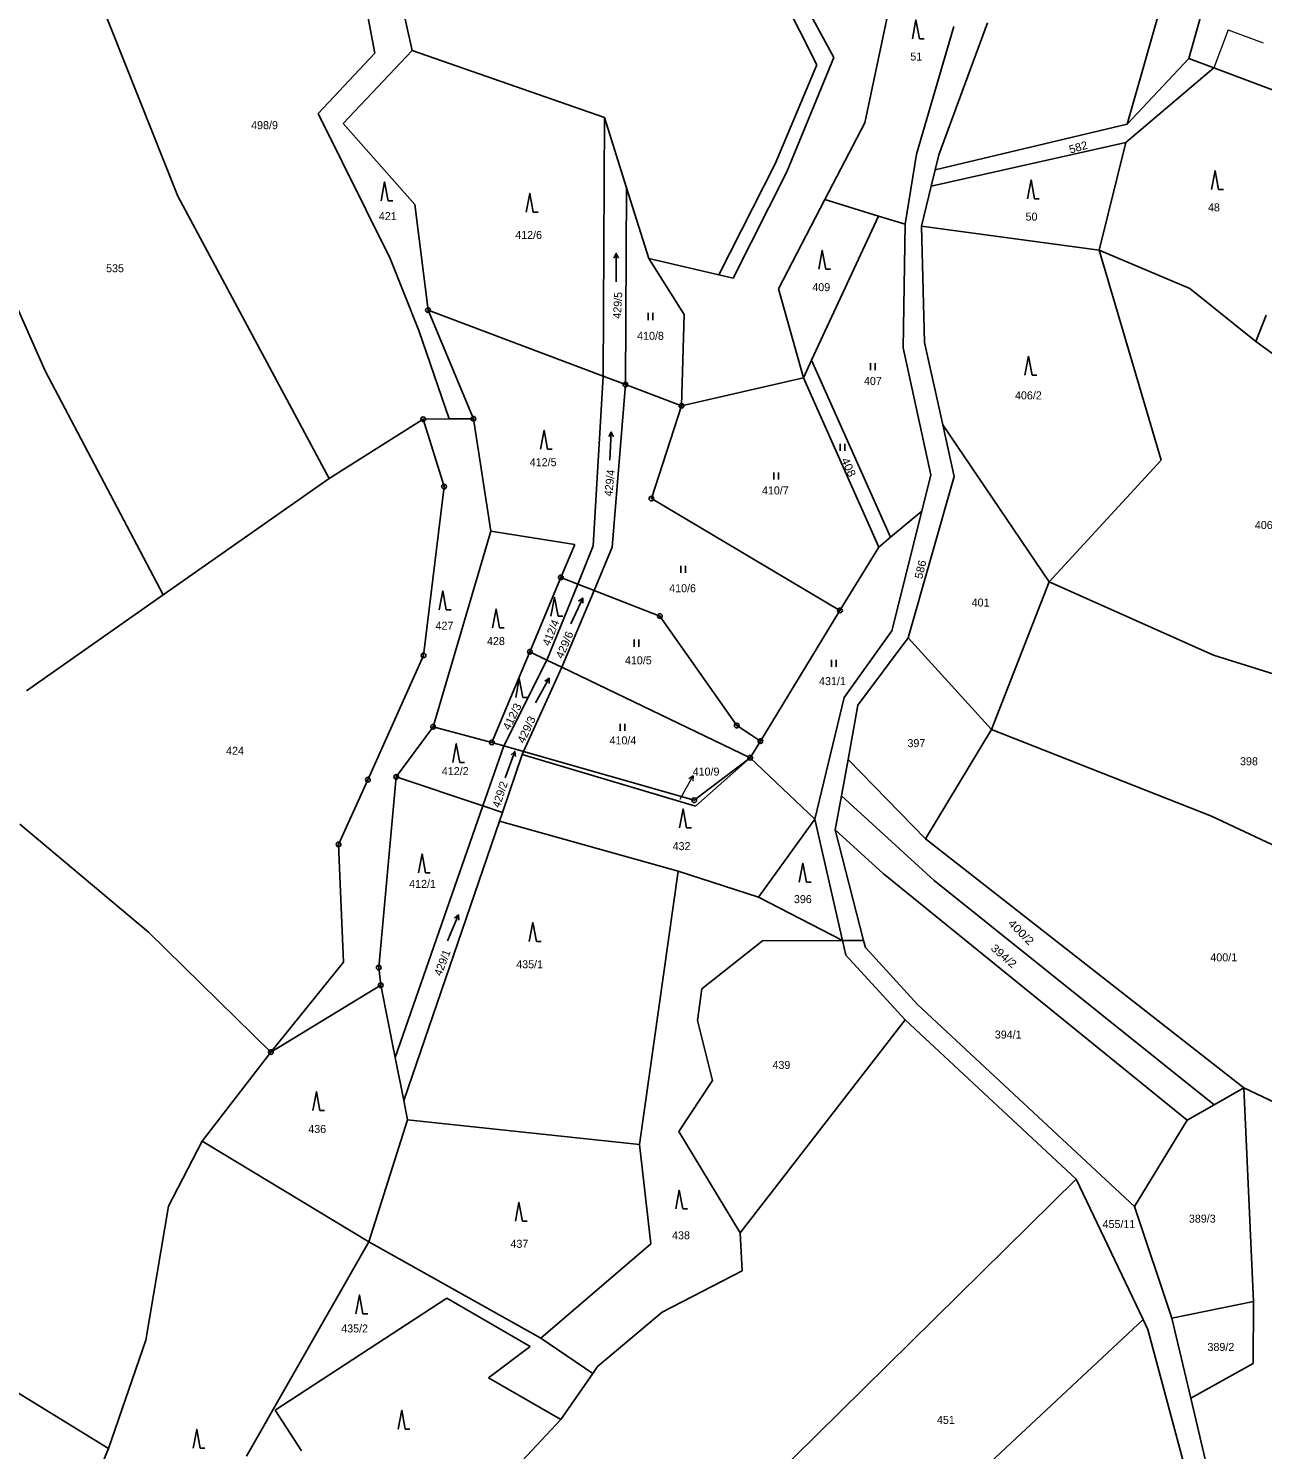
# Model space of a CAD drawing. Extents: x -664548 to -662415, y -1069720 to -1068208.
# Drawn here: x -663871.7 to -663609.5, y -1069397.8 to -1069095.9 of the extents above; entities that cross this region are included whole.
import ezdxf

# ---------------------------------------------------------------- set-up
doc = ezdxf.new("R2010")
doc.units = 0
doc.header["$LTSCALE"] = 0.68
for name, color, linetype, lineweight in [('1', 7, 'Continuous', 25), ('3', 7, 'Continuous', 25), ('4', 7, 'Continuous', 13), ('7', 7, 'Continuous', 13), ('8', 7, 'Continuous', 25)]:
    doc.layers.add(name, color=color, linetype=linetype, lineweight=lineweight)
doc.layers.add('2', color=7, linetype='Continuous')

msp = doc.modelspace()

# ---------------------------------------------------------------- linework, layer by layer
at = {"layer": '1'}
for p, q in [((-663638.3, -1069116.25), (-663622.82, -1069062.07)), ((-663865.77, -1069066.56), (-663839.98, -1069131.55)), ((-663616.65, -1069071.57), (-663625.2, -1069102.36)), ((-663801.58, -1069082.65), (-663798.08, -1069101.18)), ((-663790.14, -1069100.67), (-663794.6, -1069080.65)), ((-663715.38, -1069081.53), (-663704.24, -1069103.68)), ((-663711.53, -1069081.92), (-663700.58, -1069102.12)), ((-663694.06, -1069115.97), (-663686.64, -1069081.11)), ((-663678.33, -1069122.82), (-663667.95, -1069094.79)), ((-663899.9, -1069096.97), (-663868.16, -1069168.67)), ((-663675.12, -1069095.52), (-663683.05, -1069122.67)), ((-663804.84, -1069116.14), (-663790.14, -1069100.67)), ((-663749.29, -1069114.9), (-663790.14, -1069100.67)), ((-663798.08, -1069101.18), (-663810.11, -1069114.01)), ((-663704.24, -1069103.68), (-663713.1, -1069124.73)), ((-663700.58, -1069102.12), (-663710.58, -1069126.44)), ((-663625.2, -1069102.36), (-663638.3, -1069116.25)), ((-663625.2, -1069102.36), (-663619.9, -1069104.35)), ((-663638.58, -1069120.21), (-663619.9, -1069104.35)), ((-663619.9, -1069104.35), (-663602.12, -1069111.05)), ((-663810.11, -1069114.01), (-663794.88, -1069144.81)), ((-663789.58, -1069133.35), (-663804.84, -1069116.14)), ((-663749.63, -1069169.82), (-663749.29, -1069114.9)), ((-663749.29, -1069114.9), (-663744.62, -1069129.84)), ((-663702.52, -1069132.27), (-663694.06, -1069115.97)), ((-663638.3, -1069116.25), (-663679.1, -1069126)), ((-663638.58, -1069120.21), (-663679.93, -1069129.45)), ((-663644.23, -1069143.02), (-663638.58, -1069120.21)), ((-663713.1, -1069124.73), (-663725.04, -1069148.29)), ((-663683.05, -1069122.67), (-663685.44, -1069137.54)), ((-663679.1, -1069126), (-663678.33, -1069122.82)), ((-663710.58, -1069126.44), (-663722.02, -1069148.99)), ((-663679.93, -1069129.45), (-663679.1, -1069126)), ((-663744.88, -1069171.62), (-663744.62, -1069129.84)), ((-663744.62, -1069129.84), (-663739.93, -1069144.81)), ((-663681.98, -1069137.94), (-663679.93, -1069129.45)), ((-663807.82, -1069191.54), (-663839.98, -1069131.55)), ((-663786.81, -1069155.78), (-663789.58, -1069133.35)), ((-663712.38, -1069151.25), (-663702.52, -1069132.27)), ((-663691.09, -1069135.8), (-663702.52, -1069132.27)), ((-663705.32, -1069166.39), (-663691.09, -1069135.8)), ((-663685.44, -1069137.54), (-663691.09, -1069135.8)), ((-663685.44, -1069137.54), (-663685.91, -1069163.82)), ((-663681.35, -1069162.63), (-663681.98, -1069137.94)), ((-663644.23, -1069143.02), (-663681.98, -1069137.94)), ((-663644.23, -1069143.02), (-663624.96, -1069151.22)), ((-663631.05, -1069187.68), (-663644.23, -1069143.02)), ((-663794.88, -1069144.81), (-663788.78, -1069160.08)), ((-663725.04, -1069148.29), (-663739.93, -1069144.81)), ((-663739.93, -1069144.81), (-663732.4, -1069156.73)), ((-663722.02, -1069148.99), (-663725.04, -1069148.29)), ((-663707.06, -1069170.14), (-663712.38, -1069151.25)), ((-663624.96, -1069151.22), (-663610.98, -1069162.48)), ((-663777.17, -1069178.85), (-663786.81, -1069155.78)), ((-663786.81, -1069155.78), (-663749.63, -1069169.82)), ((-663732.4, -1069156.73), (-663732.98, -1069176.11)), ((-663610.98, -1069162.48), (-663608.81, -1069156.86)), ((-663788.78, -1069160.08), (-663782.3, -1069178.9)), ((-663685.91, -1069163.82), (-663679.99, -1069190.79)), ((-663677.47, -1069180.17), (-663681.35, -1069162.63)), ((-663610.98, -1069162.48), (-663593.01, -1069175.48)), ((-663707.06, -1069170.14), (-663705.32, -1069166.39)), ((-663688.6, -1069204.04), (-663705.32, -1069166.39)), ((-663843.03, -1069216.25), (-663868.16, -1069168.67)), ((-663751.72, -1069205.89), (-663749.63, -1069169.82)), ((-663749.63, -1069169.82), (-663744.88, -1069171.62)), ((-663732.98, -1069176.11), (-663707.06, -1069170.14)), ((-663691.08, -1069206.11), (-663707.06, -1069170.14)), ((-663747.7, -1069206.16), (-663744.88, -1069171.62)), ((-663744.88, -1069171.62), (-663732.98, -1069176.11)), ((-663732.98, -1069176.11), (-663739.35, -1069195.83)), ((-663787.83, -1069178.96), (-663807.82, -1069191.54)), ((-663787.83, -1069178.96), (-663782.3, -1069178.9)), ((-663783.39, -1069193.26), (-663787.83, -1069178.96)), ((-663782.3, -1069178.9), (-663777.17, -1069178.85)), ((-663777.17, -1069178.85), (-663773.46, -1069202.72)), ((-663654.86, -1069213.5), (-663677.47, -1069180.17)), ((-663675.05, -1069191.11), (-663677.47, -1069180.17)), ((-663654.86, -1069213.5), (-663631.05, -1069187.68)), ((-663807.82, -1069191.54), (-663843.03, -1069216.25)), ((-663684.82, -1069225.41), (-663675.05, -1069191.11)), ((-663679.99, -1069190.79), (-663681.92, -1069198.47)), ((-663787.74, -1069229.14), (-663783.39, -1069193.26)), ((-663739.35, -1069195.83), (-663699.3, -1069219.59)), ((-663688.6, -1069204.04), (-663681.92, -1069198.47)), ((-663681.92, -1069198.47), (-663688.31, -1069223.94)), ((-663773.46, -1069202.72), (-663785.73, -1069244.3)), ((-663773.46, -1069202.72), (-663755.65, -1069205.58)), ((-663755.65, -1069205.58), (-663758.58, -1069212.58)), ((-663751.72, -1069205.89), (-663755, -1069213.98)), ((-663747.7, -1069206.16), (-663751.55, -1069215.32)), ((-663699.3, -1069219.59), (-663691.08, -1069206.11)), ((-663691.08, -1069206.11), (-663688.6, -1069204.04)), ((-663758.58, -1069212.58), (-663765.18, -1069228.35)), ((-663755, -1069213.98), (-663758.58, -1069212.58)), ((-663755, -1069213.98), (-663761.54, -1069230.11)), ((-663751.55, -1069215.32), (-663758.39, -1069231.63)), ((-663751.55, -1069215.32), (-663755, -1069213.98)), ((-663737.55, -1069220.78), (-663751.55, -1069215.32)), ((-663667.09, -1069244.89), (-663654.86, -1069213.5)), ((-663620, -1069229.07), (-663654.86, -1069213.5)), ((-663843.03, -1069216.25), (-663872.12, -1069236.66)), ((-663737.55, -1069220.78), (-663721.23, -1069244.05)), ((-663716.2, -1069247.32), (-663699.3, -1069219.59)), ((-663688.31, -1069223.94), (-663698.38, -1069238.05)), ((-663695.51, -1069239.72), (-663684.82, -1069225.41)), ((-663684.82, -1069225.41), (-663667.09, -1069244.89)), ((-663799.57, -1069255.53), (-663787.74, -1069229.14)), ((-663765.18, -1069228.35), (-663773.24, -1069247.62)), ((-663761.54, -1069230.11), (-663770.69, -1069248.35)), ((-663761.54, -1069230.11), (-663765.18, -1069228.35)), ((-663758.39, -1069231.63), (-663761.54, -1069230.11)), ((-663607.07, -1069233.13), (-663620, -1069229.07)), ((-663758.39, -1069231.63), (-663766.5, -1069249.55)), ((-663718.38, -1069250.89), (-663758.39, -1069231.63)), ((-663698.38, -1069238.05), (-663704.68, -1069263.89)), ((-663697.6, -1069251.24), (-663695.51, -1069239.72)), ((-663785.73, -1069244.3), (-663793.55, -1069254.93)), ((-663773.24, -1069247.62), (-663785.73, -1069244.3)), ((-663721.23, -1069244.05), (-663718.07, -1069246.07)), ((-663718.07, -1069246.07), (-663716.2, -1069247.32)), ((-663667.09, -1069244.89), (-663681.14, -1069268.13)), ((-663667.09, -1069244.89), (-663620.38, -1069263.31)), ((-663775.13, -1069261.09), (-663770.69, -1069248.35)), ((-663770.69, -1069248.35), (-663773.24, -1069247.62)), ((-663766.5, -1069249.55), (-663770.69, -1069248.35)), ((-663718.38, -1069250.89), (-663716.2, -1069247.32)), ((-663766.79, -1069250.19), (-663771, -1069262.47)), ((-663766.5, -1069249.55), (-663766.79, -1069250.19)), ((-663729.97, -1069261.19), (-663766.79, -1069250.19)), ((-663730.27, -1069259.91), (-663766.5, -1069249.55)), ((-663730.27, -1069259.91), (-663718.38, -1069250.89)), ((-663718.38, -1069250.89), (-663729.97, -1069261.19)), ((-663704.68, -1069263.89), (-663718.38, -1069250.89)), ((-663699.01, -1069258.98), (-663697.6, -1069251.24)), ((-663681.14, -1069268.13), (-663697.6, -1069251.24)), ((-663793.55, -1069254.93), (-663797.26, -1069295.46)), ((-663775.13, -1069261.09), (-663793.55, -1069254.93)), ((-663805.8, -1069269.28), (-663799.57, -1069255.53)), ((-663793.8, -1069314.55), (-663775.13, -1069261.09)), ((-663771, -1069262.47), (-663775.13, -1069261.09)), ((-663700.32, -1069266.21), (-663699.01, -1069258.98)), ((-663679.3, -1069276.93), (-663699.01, -1069258.98)), ((-663771, -1069262.47), (-663771.65, -1069264.35)), ((-663716.58, -1069280.51), (-663704.68, -1069263.89)), ((-663704.68, -1069263.89), (-663698.75, -1069289.7)), ((-663620.38, -1069263.31), (-663570.12, -1069287)), ((-663846.2, -1069287.9), (-663873.52, -1069264.98)), ((-663771.65, -1069264.35), (-663791.98, -1069323.66)), ((-663733.7, -1069274.94), (-663771.65, -1069264.35)), ((-663690.11, -1069275.48), (-663700.32, -1069266.21)), ((-663694.28, -1069289.68), (-663700.32, -1069266.21)), ((-663804.74, -1069294.32), (-663805.8, -1069269.28)), ((-663613.49, -1069320.97), (-663681.14, -1069268.13)), ((-663741.89, -1069333.02), (-663733.7, -1069274.94)), ((-663733.7, -1069274.94), (-663716.58, -1069280.51)), ((-663625.56, -1069327.85), (-663690.11, -1069275.48)), ((-663619.83, -1069324.58), (-663679.3, -1069276.93)), ((-663820.17, -1069313.41), (-663846.2, -1069287.9)), ((-663715.75, -1069289.76), (-663728.63, -1069299.99)), ((-663694.28, -1069289.68), (-663698.75, -1069289.7)), ((-663698.75, -1069289.7), (-663698.04, -1069292.8)), ((-663693.89, -1069291.21), (-663694.28, -1069289.68)), ((-663682.82, -1069303.32), (-663693.89, -1069291.21)), ((-663820.17, -1069313.41), (-663804.74, -1069294.32)), ((-663685.43, -1069306.57), (-663698.04, -1069292.8)), ((-663797.26, -1069295.46), (-663796.86, -1069299.2)), ((-663796.86, -1069299.2), (-663820.17, -1069313.41)), ((-663796.86, -1069299.2), (-663793.8, -1069314.55)), ((-663728.63, -1069299.99), (-663729.57, -1069306.68)), ((-663636.71, -1069346.23), (-663682.82, -1069303.32)), ((-663729.57, -1069306.68), (-663726.4, -1069319.42)), ((-663720.5, -1069351.82), (-663685.43, -1069306.57)), ((-663649.12, -1069340.38), (-663685.43, -1069306.57)), ((-663820.17, -1069313.41), (-663834.81, -1069332.34)), ((-663793.8, -1069314.55), (-663791.98, -1069323.66)), ((-663726.4, -1069319.42), (-663733.53, -1069330.29)), ((-663613.49, -1069320.97), (-663619.83, -1069324.58)), ((-663613.49, -1069320.97), (-663604.26, -1069325.38)), ((-663611.5, -1069366.37), (-663613.49, -1069320.97)), ((-663791.98, -1069323.66), (-663791.16, -1069327.76)), ((-663619.83, -1069324.58), (-663625.56, -1069327.85)), ((-663791.16, -1069327.76), (-663799.35, -1069353.72)), ((-663791.16, -1069327.76), (-663741.89, -1069333.02)), ((-663733.53, -1069330.29), (-663720.5, -1069351.82)), ((-663625.56, -1069327.85), (-663636.71, -1069346.23)), ((-663834.81, -1069332.34), (-663841.91, -1069346.1)), ((-663799.35, -1069353.72), (-663834.81, -1069332.34)), ((-663741.89, -1069333.02), (-663739.46, -1069354.12)), ((-663730.63, -1069420.68), (-663649.12, -1069340.38)), ((-663649.12, -1069340.38), (-663634.92, -1069370.21)), ((-663841.91, -1069346.1), (-663846.72, -1069374.59)), ((-663628.78, -1069369.92), (-663636.71, -1069346.23)), ((-663799.35, -1069353.72), (-663825.36, -1069399.27)), ((-663799.35, -1069353.72), (-663762.86, -1069374.17)), ((-663739.46, -1069354.12), (-663762.86, -1069374.17)), ((-663720.5, -1069351.82), (-663720.07, -1069359.88)), ((-663720.07, -1069359.88), (-663737.05, -1069368.67)), ((-663782.8, -1069365.67), (-663819.27, -1069389.47)), ((-663782.8, -1069365.67), (-663765.09, -1069375.97)), ((-663611.5, -1069366.37), (-663628.78, -1069369.92)), ((-663611.54, -1069379.52), (-663611.5, -1069366.37)), ((-663737.05, -1069368.67), (-663750.8, -1069380.19)), ((-663718.73, -1069448.55), (-663634.92, -1069370.21)), ((-663634.92, -1069370.21), (-663633.89, -1069372.36)), ((-663633.89, -1069372.36), (-663626.15, -1069401.37)), ((-663624.79, -1069386.91), (-663628.78, -1069369.92)), ((-663846.72, -1069374.59), (-663854.69, -1069397.6)), ((-663762.86, -1069374.17), (-663751.82, -1069381.66)), ((-663886.73, -1069377.97), (-663854.69, -1069397.6)), ((-663765.09, -1069375.97), (-663773.97, -1069382.57)), ((-663751.82, -1069381.66), (-663758.57, -1069391.42)), ((-663750.8, -1069380.19), (-663751.82, -1069381.66)), ((-663611.54, -1069379.52), (-663624.79, -1069386.91)), ((-663758.57, -1069391.42), (-663773.97, -1069382.57)), ((-663620.97, -1069403.18), (-663624.79, -1069386.91)), ((-663819.27, -1069389.47), (-663813.67, -1069398.07)), ((-663791.3, -1069426.25), (-663758.57, -1069391.42)), ((-663854.69, -1069397.6), (-663858.93, -1069407.87))]:
    msp.add_line(p, q, dxfattribs=at)
msp.add_lwpolyline([(-663716.58, -1069280.51), (-663698.75, -1069289.7), (-663715.75, -1069289.76)], dxfattribs=at)
at = {"layer": '3'}
for p, q in [((-663682.43, -1069098.15), (-663681.434, -1069098.15)), ((-663618.87, -1069130.17), (-663617.874, -1069130.17)), ((-663795.28, -1069132.56), (-663794.284, -1069132.56)), ((-663657.96, -1069132.12), (-663656.964, -1069132.12)), ((-663764.44, -1069134.99), (-663763.444, -1069134.99)), ((-663746.841, -1069143.743), (-663746.34, -1069144.72)), ((-663702.31, -1069147.09), (-663701.314, -1069147.09)), ((-663740.081, -1069157.89), (-663740.081, -1069156.39)), ((-663739.08, -1069157.89), (-663739.08, -1069156.39)), ((-663692.801, -1069168.52), (-663692.801, -1069167.02)), ((-663691.8, -1069168.52), (-663691.8, -1069167.02)), ((-663658.51, -1069169.59), (-663657.514, -1069169.59)), ((-663747.884, -1069181.677), (-663747.434, -1069182.679)), ((-663761.42, -1069185.29), (-663760.424, -1069185.29)), ((-663699.271, -1069185.69), (-663699.271, -1069184.19)), ((-663698.27, -1069185.69), (-663698.27, -1069184.19)), ((-663713.331, -1069191.76), (-663713.331, -1069190.26)), ((-663712.33, -1069191.76), (-663712.33, -1069190.26)), ((-663733.091, -1069211.57), (-663733.091, -1069210.07)), ((-663732.09, -1069211.57), (-663732.09, -1069210.07)), ((-663753.957, -1069216.969), (-663753.916, -1069218.067)), ((-663782.92, -1069219.45), (-663781.924, -1069219.45)), ((-663759.19, -1069220.8), (-663758.194, -1069220.8)), ((-663771.61, -1069223.29), (-663770.614, -1069223.29)), ((-663743.041, -1069227.28), (-663743.041, -1069225.78)), ((-663742.04, -1069227.28), (-663742.04, -1069225.78)), ((-663701.131, -1069231.54), (-663701.131, -1069230.04)), ((-663700.13, -1069231.54), (-663700.13, -1069230.04)), ((-663761.05, -1069233.975), (-663761.085, -1069235.073)), ((-663766.67, -1069238.06), (-663765.674, -1069238.06)), ((-663745.971, -1069245.14), (-663745.971, -1069243.64)), ((-663744.97, -1069245.14), (-663744.97, -1069243.64)), ((-663780.05, -1069251.91), (-663779.054, -1069251.91)), ((-663768.37, -1069249.518), (-663768.233, -1069250.607)), ((-663731.87, -1069265.73), (-663730.874, -1069265.73)), ((-663787.32, -1069275.31), (-663786.324, -1069275.31)), ((-663706.45, -1069277.29), (-663705.454, -1069277.29)), ((-663780.333, -1069284.276), (-663780.253, -1069285.371)), ((-663763.8, -1069289.88), (-663762.804, -1069289.88)), ((-663809.78, -1069325.83), (-663808.784, -1069325.83)), ((-663732.68, -1069346.73), (-663731.684, -1069346.73)), ((-663766.76, -1069349.33), (-663765.764, -1069349.33)), ((-663800.62, -1069369), (-663799.624, -1069369)), ((-663791.64, -1069393.49), (-663790.644, -1069393.49)), ((-663835.18, -1069397.54), (-663834.184, -1069397.54))]:
    msp.add_line(p, q, dxfattribs=at)
for points in [[(-663682.43, -1069098.15), (-663683.18, -1069094.15), (-663683.93, -1069098.15)], [(-663657.96, -1069132.12), (-663658.71, -1069128.12), (-663659.46, -1069132.12)], [(-663618.87, -1069130.17), (-663619.62, -1069126.17), (-663620.37, -1069130.17)], [(-663795.28, -1069132.56), (-663796.03, -1069128.56), (-663796.78, -1069132.56)], [(-663764.44, -1069134.99), (-663765.19, -1069130.99), (-663765.94, -1069134.99)], [(-663702.31, -1069147.09), (-663703.06, -1069143.09), (-663703.81, -1069147.09)], [(-663746.841, -1069149.743), (-663746.841, -1069143.743), (-663747.343, -1069144.72)], [(-663658.51, -1069169.59), (-663659.26, -1069165.59), (-663660.01, -1069169.59)], [(-663761.42, -1069185.29), (-663762.17, -1069181.29), (-663762.92, -1069185.29)], [(-663748.198, -1069187.669), (-663747.884, -1069181.677), (-663748.435, -1069182.627)], [(-663782.92, -1069219.45), (-663783.67, -1069215.45), (-663784.42, -1069219.45)], [(-663759.19, -1069220.8), (-663759.94, -1069216.8), (-663760.69, -1069220.8)], [(-663756.493, -1069222.407), (-663753.957, -1069216.969), (-663754.825, -1069217.643)], [(-663771.61, -1069223.29), (-663772.36, -1069219.29), (-663773.11, -1069223.29)], [(-663763.959, -1069239.223), (-663761.05, -1069233.975), (-663761.962, -1069234.587)], [(-663766.67, -1069238.06), (-663767.42, -1069234.06), (-663768.17, -1069238.06)], [(-663780.05, -1069251.91), (-663780.8, -1069247.91), (-663781.55, -1069251.91)], [(-663770.422, -1069255.156), (-663768.37, -1069249.518), (-663769.175, -1069250.264)], [(-663731.87, -1069265.73), (-663732.62, -1069261.73), (-663733.37, -1069265.73)], [(-663787.32, -1069275.31), (-663788.07, -1069271.31), (-663788.82, -1069275.31)], [(-663706.45, -1069277.29), (-663707.2, -1069273.29), (-663707.95, -1069277.29)], [(-663782.678, -1069289.799), (-663780.333, -1069284.276), (-663781.177, -1069284.98)], [(-663763.8, -1069289.88), (-663764.55, -1069285.88), (-663765.3, -1069289.88)], [(-663809.78, -1069325.83), (-663810.53, -1069321.83), (-663811.28, -1069325.83)], [(-663766.76, -1069349.33), (-663767.51, -1069345.33), (-663768.26, -1069349.33)], [(-663732.68, -1069346.73), (-663733.43, -1069342.73), (-663734.18, -1069346.73)], [(-663800.62, -1069369), (-663801.37, -1069365), (-663802.12, -1069369)], [(-663791.64, -1069393.49), (-663792.39, -1069389.49), (-663793.14, -1069393.49)], [(-663835.18, -1069397.54), (-663835.93, -1069393.54), (-663836.68, -1069397.54)]]:
    msp.add_lwpolyline(points, dxfattribs=at)
at = {"layer": '4'}
for q in [(-663619.9, -1069104.35), (-663609.42, -1069099.01)]:
    msp.add_line((-663616.84, -1069096.22), q, dxfattribs=at)
at = {"layer": '7'}
msp.add_line((-663730.485, -1069254.725), (-663731.409, -1069255.358), dxfattribs=at)
msp.add_lwpolyline([(-663733.22, -1069259.68), (-663731.94, -1069257.35), (-663730.485, -1069254.725), (-663730.533, -1069255.844)], dxfattribs=at)
at = {"layer": '8'}
for centre, radius in [((-663786.81, -1069155.7799), 0.5), ((-663786.81, -1069155.7799), 0.0303), ((-663744.88, -1069171.6199), 0.5), ((-663744.88, -1069171.6199), 0.0303), ((-663732.98, -1069176.1099), 0.5), ((-663732.98, -1069176.1099), 0.0303), ((-663787.83, -1069178.9599), 0.5), ((-663787.83, -1069178.9599), 0.0303), ((-663777.17, -1069178.8499), 0.5), ((-663777.17, -1069178.8499), 0.0303), ((-663783.39, -1069193.2599), 0.5), ((-663783.39, -1069193.2599), 0.0303), ((-663739.35, -1069195.8299), 0.5), ((-663739.35, -1069195.8299), 0.0303), ((-663758.58, -1069212.5799), 0.5), ((-663758.58, -1069212.5799), 0.0303), ((-663737.55, -1069220.7799), 0.5), ((-663737.55, -1069220.7799), 0.0303), ((-663699.3, -1069219.5899), 0.5), ((-663699.3, -1069219.5899), 0.0303), ((-663765.18, -1069228.3499), 0.5), ((-663787.74, -1069229.1399), 0.5), ((-663787.74, -1069229.1399), 0.0303), ((-663765.18, -1069228.3499), 0.0303), ((-663785.73, -1069244.2999), 0.5), ((-663785.73, -1069244.2999), 0.0303), ((-663721.23, -1069244.0499), 0.5), ((-663721.23, -1069244.0499), 0.0303), ((-663773.24, -1069247.6199), 0.5), ((-663773.24, -1069247.6199), 0.0303), ((-663716.2, -1069247.3199), 0.5), ((-663716.2, -1069247.3199), 0.0303), ((-663718.38, -1069250.8899), 0.5), ((-663718.38, -1069250.8899), 0.0303), ((-663799.57, -1069255.5299), 0.5), ((-663793.55, -1069254.9299), 0.5), ((-663793.55, -1069254.9299), 0.0303), ((-663799.57, -1069255.5299), 0.0303), ((-663730.27, -1069259.9099), 0.5), ((-663730.27, -1069259.9099), 0.0303), ((-663805.8, -1069269.2799), 0.5), ((-663805.8, -1069269.2799), 0.0303), ((-663797.26, -1069295.4599), 0.5), ((-663797.26, -1069295.4599), 0.0303), ((-663796.86, -1069299.1999), 0.5), ((-663796.86, -1069299.1999), 0.0303), ((-663820.17, -1069313.4099), 0.5), ((-663820.17, -1069313.4099), 0.0303)]:
    msp.add_circle(centre, radius, dxfattribs=at)

# ---------------------------------------------------------------- texts
at = {"layer": '2'}
for s, p in [('51', (-663684.36, -1069102.765)), ('498/9', (-663824.38, -1069117.344)), ('48', (-663621.14, -1069134.814)), ('421', (-663797.25, -1069136.665)), ('50', (-663659.88, -1069136.775)), ('412/6', (-663768.28, -1069140.665)), ('535', (-663855.19, -1069147.735)), ('409', (-663705.18, -1069151.755)), ('410/8', (-663742.39, -1069162.094)), ('407', (-663694.21, -1069171.675)), ('406/2', (-663662.13, -1069174.745)), ('412/5', (-663765.2, -1069188.935)), ('410/7', (-663715.88, -1069194.945)), ('406/1', (-663611.18, -1069202.285)), ('410/6', (-663735.58, -1069215.715)), ('401', (-663671.34, -1069218.745)), ('427', (-663785.21, -1069223.675)), ('428', (-663774.28, -1069226.935)), ('410/5', (-663744.98, -1069231.025)), ('431/1', (-663703.75, -1069235.445)), ('424', (-663829.71, -1069250.245)), ('410/4', (-663748.25, -1069248.035)), ('397', (-663684.97, -1069248.615)), ('398', (-663614.33, -1069252.465)), ('412/2', (-663783.87, -1069254.564)), ('410/9', (-663730.59, -1069254.665)), ('432', (-663734.85, -1069270.495)), ('412/1', (-663790.82, -1069278.515)), ('396', (-663709.09, -1069281.755)), ('435/1', (-663768.07, -1069295.594)), ('400/1', (-663620.63, -1069294.125)), ('394/1', (-663666.42, -1069310.525)), ('439', (-663713.64, -1069316.985)), ('436', (-663812.24, -1069330.584)), ('389/3', (-663625.19, -1069349.625)), ('438', (-663734.97, -1069353.165)), ('455/11', (-663643.53, -1069350.775)), ('437', (-663769.3, -1069354.975)), ('435/2', (-663805.24, -1069372.955)), ('389/2', (-663621.24, -1069376.885)), ('451', (-663678.71, -1069392.375))]:
    msp.add_text(s, height=1.7, dxfattribs=at).set_placement(p)
for s, rotation, width, p in [('582', 16, 1.05, (-663650.372, -1069122.548)), ('408', 294, 1.1, (-663699.078, -1069187.592)), ('586', 77, 1.05, (-663681.835, -1069213.005)), ('429/6', 67, 1.05, (-663758.198, -1069229.966)), ('412/3', 64, 1.05, (-663769.488, -1069245.186)), ('429/3', 65, 1.05, (-663766.394, -1069247.959)), ('400/2', 315, 1.15, (-663663.75, -1069286.21)), ('394/2', 319, 1.1, (-663667.418, -1069291.56))]:
    msp.add_text(s, height=1.7, rotation=rotation, dxfattribs=dict(at, width=width)).set_placement(p)
for s, rotation, p in [('429/5', 87, (-663745.835, -1069157.652)), ('429/4', 84, (-663747.697, -1069195.424)), ('412/4', 68, (-663761.005, -1069227.269)), ('429/2', 72, (-663771.595, -1069261.621)), ('429/1', 69, (-663784.003, -1069297.372))]:
    msp.add_text(s, height=1.7, rotation=rotation, dxfattribs=at).set_placement(p)

doc.saveas('drawing.dxf')
